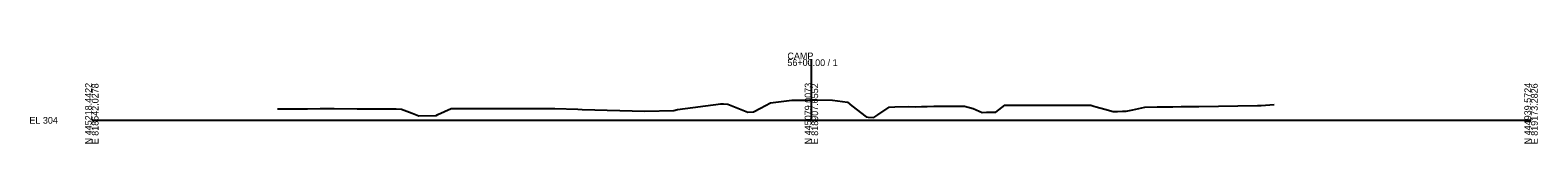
# Model space of a CAD drawing. Extents: x -26 to 603, y -10 to 2524.
# Drawn here: x -26 to 603, y -10 to 28 of the extents above; entities that cross this region are included whole.
import ezdxf

# ---------------------------------------------------------------- set-up
doc = ezdxf.new("R2010")
doc.units = 0
doc.layers.add('DESIGN - SHEET - Light Grid', color=7, linetype='Continuous')
doc.layers.add('SURVEY - GROUND - Top of Ground', color=7, linetype='Continuous')

msp = doc.modelspace()

# ---------------------------------------------------------------- linework, layer by layer
at = {"layer": 'DESIGN - SHEET - Light Grid'}
for p, q in [((300, 0), (300, 25.43)), ((0, 0), (300, 0)), ((300, 0), (600, 0))]:
    msp.add_line(p, q, dxfattribs=at)
at = {"layer": 'SURVEY - GROUND - Top of Ground'}
msp.add_lwpolyline([(77.46, 4.76), (83.75, 4.8), (89.31, 4.83), (89.92, 4.83), (95.21, 4.85), (96.1, 4.85), (101.1, 4.87), (110.69, 4.84), (114.94, 4.82), (118.44, 4.83), (124.78, 4.8), (125.99, 4.8), (126.91, 4.8), (129.18, 4.7), (133.54, 2.99), (136.37, 1.87), (143.61, 2.04), (144.33, 2.39), (149.87, 4.88), (155, 4.88), (164.22, 4.89), (192.98, 4.9), (202.61, 4.65), (204.49, 4.51), (230.49, 3.87), (242.58, 4.08), (244.14, 4.47), (262.26, 6.8), (263.32, 6.89), (265.1, 6.65), (273.53, 3.37), (275.8, 3.49), (278.79, 5.11), (282.96, 7.3), (287.38, 7.83), (291.9, 8.37), (298.48, 8.45), (300, 8.47), (300.36, 8.48), (301.74, 8.46), (308.86, 8.38), (312.92, 7.79), (314.98, 7.49), (316.9, 5.96), (322.86, 1.37), (323.63, 1.32), (326.08, 1.15), (327.71, 2.24), (332.41, 5.53), (334.79, 5.62), (340.55, 5.7), (343.23, 5.66), (345.92, 5.78), (348.2, 5.75), (351.09, 5.89), (354.8, 5.9), (360.22, 5.9), (362.09, 5.89), (362.57, 5.89), (363.76, 5.9), (367.41, 4.91), (371.19, 3.31), (372.95, 3.34), (376.89, 3.39), (380.7, 6.37), (382.54, 6.37), (385.97, 6.36), (402.65, 6.34), (416.44, 6.3), (417.67, 5.94), (418.76, 5.64), (422.34, 4.61), (425.79, 3.68), (426.55, 3.7), (427.61, 3.73), (429.75, 3.78), (431.15, 3.82), (433.99, 4.39), (438.94, 5.48), (444.11, 5.55), (445.02, 5.56), (449.11, 5.62), (450.63, 5.64), (454.13, 5.68), (456.12, 5.71), (459.16, 5.75), (461.51, 5.78), (485.97, 6.14), (487.45, 6.16), (492.89, 6.53)], dxfattribs=at)

# ---------------------------------------------------------------- texts
at = {"layer": 'DESIGN - SHEET - Light Grid'}
for s, p in [('56+00.00 / 1', (290, 22.63)), ('CAMP', (290, 25.43)), ('EL 304', (-26, -1.4))]:
    msp.add_text(s, height=2.8, dxfattribs=at).set_placement(p)
for s, p in [('N 445218.4422', (0, -10)), ('E 818642.0278', (2.8, -10)), ('N 445079.0073', (300, -10)), ('E 818907.6552', (302.8, -10)), ('N 444939.5724', (600, -10)), ('E 819173.2826', (602.8, -10))]:
    msp.add_text(s, height=2.8, rotation=90, dxfattribs=at).set_placement(p)

doc.saveas('drawing.dxf')
